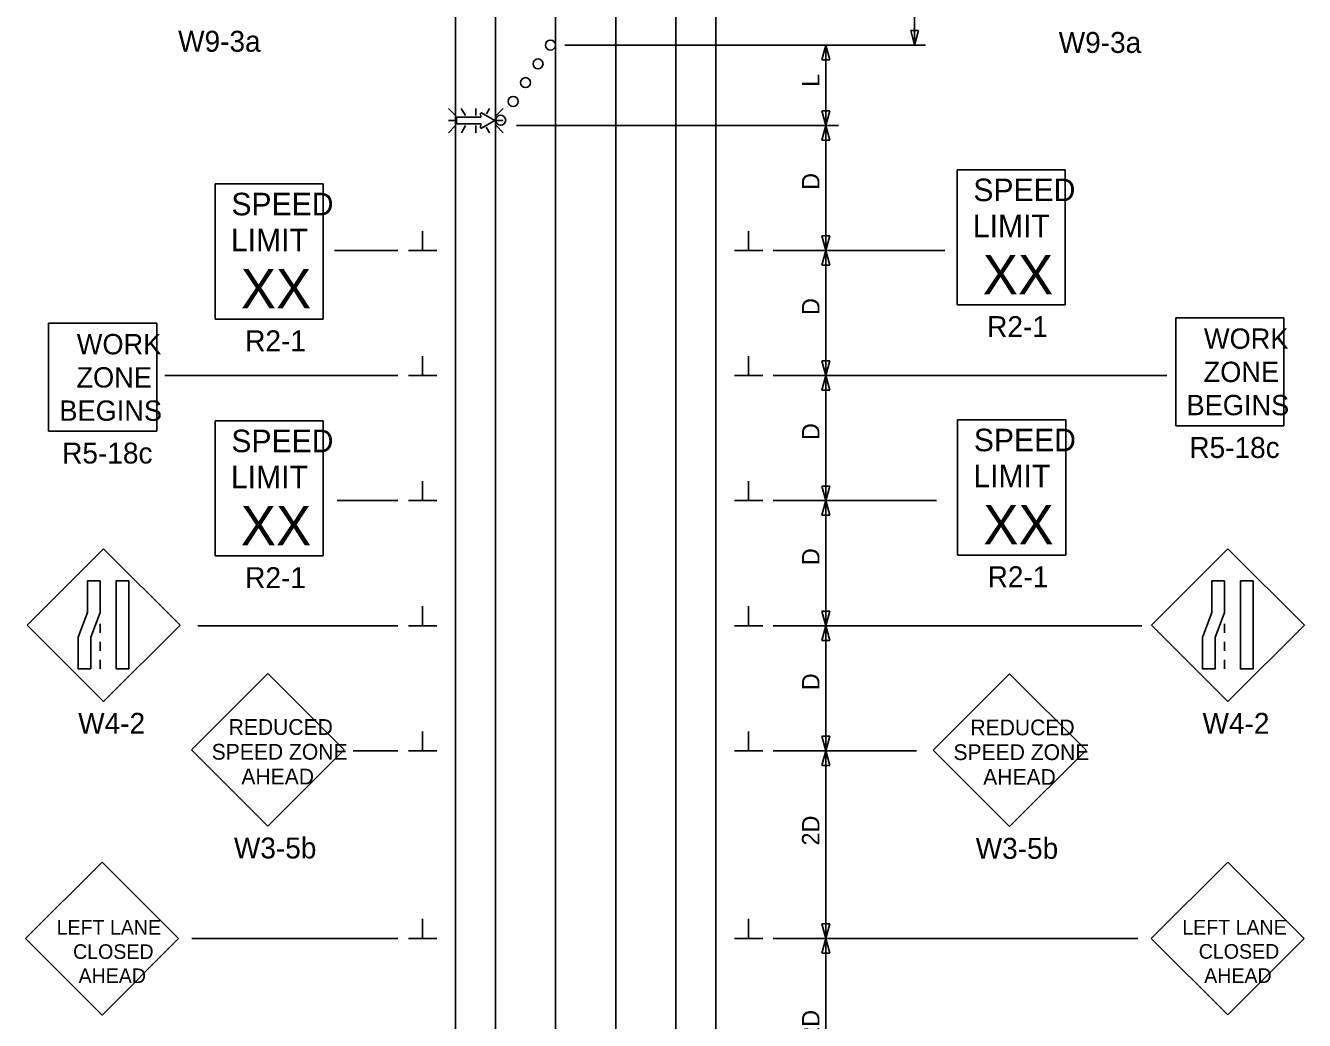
# Model space of a CAD drawing. Extents: x 16726 to 18482, y 5650 to 7013.
# Drawn here: x 16732 to 17243, y 6168 to 6566 of the extents above; entities that cross this region are included whole.
import ezdxf

# ---------------------------------------------------------------- set-up
doc = ezdxf.new("R2010")
doc.units = 0
for name, color, linetype in [('ALI_LEGAL_EX', 7, 'Continuous'), ('Level 6', 7, 'Continuous'), ('PAVT_EDGE_EX', 7, 'Continuous'), ('TRAFFIC_SIGNS_PR', 7, 'Continuous'), ('TYPICAL_TEXT_DIMEN_PR', 7, 'Continuous')]:
    doc.layers.add(name, color=color, linetype=linetype)

msp = doc.modelspace()

# ---------------------------------------------------------------- linework, layer by layer
at = {"layer": 'ALI_LEGAL_EX'}
for p, q in [((16943.36, 7013.47), (16943.36, 6195.33)), ((16967.36, 7013.47), (16967.36, 6195.33)), ((16943.36, 6961.56), (16943.36, 6097.65)), ((16967.36, 6961.56), (16967.36, 6097.65))]:
    msp.add_line(p, q, dxfattribs=at)
for points in [[(16943.36, 6524.34), (16943.36, 6499.34)], [(16943.36, 6524.34), (16943.36, 6499.34)], [(16943.36, 6524.34), (16943.36, 6499.34)], [(16943.36, 6524.34), (16943.36, 6499.34)], [(16943.36, 6524.34), (16943.36, 6499.34)], [(16967.36, 6524.34), (16967.36, 6499.34)], [(16967.36, 6524.34), (16967.36, 6499.34)], [(16967.36, 6524.34), (16967.36, 6499.34)], [(16967.36, 6524.34), (16967.36, 6499.34)], [(16967.36, 6524.34), (16967.36, 6499.34)], [(16943.36, 6424.34), (16943.36, 6399.34)], [(16943.36, 6424.34), (16943.36, 6399.34)], [(16943.36, 6424.34), (16943.36, 6399.34)], [(16943.36, 6424.34), (16943.36, 6399.34)], [(16943.36, 6424.34), (16943.36, 6399.34)], [(16967.36, 6424.34), (16967.36, 6399.34)], [(16967.36, 6424.34), (16967.36, 6399.34)], [(16967.36, 6424.34), (16967.36, 6399.34)], [(16967.36, 6424.34), (16967.36, 6399.34)], [(16967.36, 6424.34), (16967.36, 6399.34)], [(16943.36, 6324.34), (16943.36, 6299.34)], [(16943.36, 6324.34), (16943.36, 6299.34)], [(16943.36, 6324.34), (16943.36, 6299.34)], [(16943.36, 6324.34), (16943.36, 6299.34)], [(16943.36, 6324.34), (16943.36, 6299.34)], [(16967.36, 6324.34), (16967.36, 6299.34)], [(16967.36, 6324.34), (16967.36, 6299.34)], [(16967.36, 6324.34), (16967.36, 6299.34)], [(16967.36, 6324.34), (16967.36, 6299.34)], [(16967.36, 6324.34), (16967.36, 6299.34)], [(16943.36, 6224.34), (16943.36, 6199.34)], [(16943.36, 6224.34), (16943.36, 6199.34)], [(16943.36, 6224.34), (16943.36, 6199.34)], [(16943.36, 6224.34), (16943.36, 6199.34)], [(16967.36, 6224.34), (16967.36, 6199.34)], [(16967.36, 6224.34), (16967.36, 6199.34)], [(16967.36, 6224.34), (16967.36, 6199.34)], [(16967.36, 6224.34), (16967.36, 6199.34)], [(16967.36, 6224.34), (16967.36, 6199.34)]]:
    msp.add_lwpolyline(points, dxfattribs=at)
at = {"layer": 'Level 6'}
for p, q in [((16828.35, 6307.2), (16797.81, 6276.66)), ((16858.9, 6276.66), (16828.35, 6307.2)), ((16797.81, 6276.66), (16828.35, 6246.11)), ((16828.35, 6246.11), (16858.9, 6276.66))]:
    msp.add_line(p, q, dxfattribs=at)
at = {"layer": 'PAVT_EDGE_EX'}
for p, q in [((16903.36, 6926.44), (16903.36, 6057.56)), ((16919.36, 6926.44), (16919.36, 6057.56)), ((16991.36, 6926.44), (16991.36, 6057.56)), ((17007.36, 6926.44), (17007.36, 6057.56))]:
    msp.add_line(p, q, dxfattribs=at)
at = {"layer": 'TRAFFIC_SIGNS_PR'}
for p, q in [((16903.38, 6530.22), (16900.56, 6533.04)), ((16905.67, 6533.04), (16907.3, 6530.22)), ((16911.46, 6530.22), (16911.46, 6533.04)), ((16916.93, 6533.04), (16915.72, 6530.95)), ((16922.37, 6533.04), (16919.55, 6530.22)), ((16903.38, 6528.19), (16900.56, 6528.19)), ((16903.38, 6526.16), (16900.56, 6523.34)), ((16907.33, 6526.16), (16905.7, 6523.34)), ((16911.46, 6526.16), (16911.46, 6523.34)), ((16919.55, 6528.19), (16922.37, 6528.19)), ((16922.37, 6523.34), (16919.55, 6526.16)), ((16915.65, 6525.52), (16916.91, 6523.34)), ((17103.8, 6508.51), (17147, 6508.51)), ((17103.8, 6454.51), (17103.8, 6508.51)), ((17147, 6454.51), (17147, 6508.51)), ((16807.3, 6502.86), (16850.5, 6502.86)), ((16807.3, 6448.86), (16807.3, 6502.86)), ((16850.5, 6448.86), (16850.5, 6502.86)), ((17103.8, 6454.51), (17147, 6454.51)), ((16740.76, 6403.98), (16740.76, 6447.18)), ((16740.76, 6447.18), (16783.96, 6447.18)), ((16783.96, 6403.98), (16783.96, 6447.18)), ((16807.3, 6448.86), (16850.5, 6448.86)), ((17191.21, 6406.19), (17191.21, 6449.39)), ((17191.21, 6449.39), (17234.41, 6449.39)), ((17234.41, 6406.19), (17234.41, 6449.39)), ((16740.76, 6403.98), (16783.96, 6403.98)), ((16807.3, 6408.17), (16850.5, 6408.17)), ((16807.3, 6354.17), (16807.3, 6408.17)), ((16850.5, 6354.17), (16850.5, 6408.17)), ((17103.99, 6408.54), (17147.19, 6408.54)), ((17103.99, 6354.54), (17103.99, 6408.54)), ((17147.19, 6354.54), (17147.19, 6408.54)), ((17191.21, 6406.19), (17234.41, 6406.19)), ((16762.75, 6357.04), (16732.2, 6326.5)), ((16793.29, 6326.5), (16762.75, 6357.04)), ((16807.3, 6354.17), (16850.5, 6354.17)), ((17103.99, 6354.54), (17147.19, 6354.54)), ((17212.05, 6357.02), (17181.5, 6326.47)), ((17242.6, 6326.47), (17212.05, 6357.02)), ((16761.34, 6327.05), (16761.34, 6323.45)), ((17210.65, 6327.03), (17210.65, 6323.43)), ((16732.2, 6326.5), (16762.75, 6295.95)), ((16762.75, 6295.95), (16793.29, 6326.5)), ((17181.5, 6326.47), (17212.05, 6295.93)), ((17212.05, 6295.93), (17242.6, 6326.47)), ((16761.34, 6319.85), (16761.34, 6316.25)), ((17210.65, 6319.83), (17210.65, 6316.23)), ((16761.34, 6312.65), (16761.34, 6309.05)), ((17210.65, 6312.63), (17210.65, 6309.03)), ((17124.79, 6307.05), (17094.25, 6276.5)), ((17155.34, 6276.5), (17124.79, 6307.05)), ((17094.25, 6276.5), (17124.79, 6245.96)), ((17124.79, 6245.96), (17155.34, 6276.5)), ((16762.09, 6231.73), (16731.55, 6201.19)), ((16792.64, 6201.19), (16762.09, 6231.73)), ((17211.93, 6231.82), (17181.38, 6201.27)), ((17242.47, 6201.27), (17211.93, 6231.82)), ((16731.55, 6201.19), (16762.09, 6170.64)), ((16762.09, 6170.64), (16792.64, 6201.19)), ((17181.38, 6201.27), (17211.93, 6170.72)), ((17211.93, 6170.72), (17242.47, 6201.27))]:
    msp.add_line(p, q, dxfattribs=at)
for points in [[(16913.29, 6530.87), (16913.52, 6529.58), (16903.8, 6529.58), (16903.8, 6526.83), (16913.52, 6526.83), (16913.29, 6525.53)], [(16913.79, 6525.18), (16919.1, 6528.19), (16913.79, 6531.23)]]:
    msp.add_lwpolyline(points, dxfattribs=at)
for points in [[(16761.34, 6344.2), (16761.34, 6331.62), (16757.58, 6321.63), (16757.58, 6309.05), (16752.53, 6309.05), (16752.53, 6321.63), (16756.29, 6331.62), (16756.29, 6344.2)], [(16772.75, 6344.2), (16772.75, 6309.05), (16767.69, 6309.05), (16767.69, 6344.2)], [(17210.65, 6344.18), (17210.65, 6331.6), (17206.89, 6321.6), (17206.89, 6309.03), (17201.83, 6309.03), (17201.83, 6321.6), (17205.59, 6331.6), (17205.59, 6344.18)], [(17222.05, 6344.18), (17222.05, 6309.03), (17217, 6309.03), (17217, 6344.18)]]:
    msp.add_lwpolyline(points, close=True, dxfattribs=at)
for centre in [(16941.29, 6558.37), (16936.33, 6550.85), (16931.36, 6543.35), (16926.39, 6535.85), (16921.42, 6528.34)]:
    msp.add_circle(centre, 2, dxfattribs=at)
for centre, start, end in [((16913.62, 6530.93), 61.4833, 189.9593), ((16913.62, 6525.47), 170.7308, 298.8916)]:
    msp.add_arc(centre, 0.341, start, end, dxfattribs=at)
at = {"layer": 'TYPICAL_TEXT_DIMEN_PR'}
for p, q in [((17086.84, 6676.24), (17086.84, 6558.37)), ((17086.84, 6558.37), (17085.27, 6564.23)), ((17085.27, 6564.23), (17086.84, 6564.23)), ((17086.84, 6564.23), (17088.41, 6564.23)), ((17088.41, 6564.23), (17086.84, 6558.37)), ((16947.11, 6558.37), (17091.17, 6558.37)), ((17049.79, 6552.51), (17051.36, 6558.37)), ((17051.36, 6558.37), (17051.36, 6526.26)), ((17051.36, 6558.37), (17052.93, 6552.51)), ((17051.36, 6552.51), (17049.79, 6552.51)), ((17052.93, 6552.51), (17051.36, 6552.51)), ((17051.36, 6526.26), (17049.79, 6532.12)), ((17049.79, 6532.12), (17051.36, 6532.12)), ((17051.36, 6532.12), (17052.93, 6532.12)), ((17052.93, 6532.12), (17051.36, 6526.26)), ((16927.76, 6526.26), (17056.36, 6526.26)), ((17049.79, 6520.4), (17051.36, 6526.26)), ((17051.36, 6526.26), (17051.36, 6476.26)), ((17051.36, 6526.26), (17052.93, 6520.4)), ((17051.36, 6520.4), (17049.79, 6520.4)), ((17052.93, 6520.4), (17051.36, 6520.4)), ((16890.23, 6476.26), (16890.23, 6484.05)), ((17020.48, 6476.26), (17020.48, 6484.05)), ((17051.36, 6476.26), (17049.79, 6482.12)), ((17049.79, 6482.12), (17051.36, 6482.12)), ((17051.36, 6482.12), (17052.93, 6482.12)), ((17052.93, 6482.12), (17051.36, 6476.26)), ((16855.01, 6476.26), (16880.36, 6476.26)), ((16884.61, 6476.26), (16895.86, 6476.26)), ((17026.11, 6476.26), (17014.86, 6476.26)), ((17030.36, 6476.26), (17098.92, 6476.26)), ((17049.79, 6470.4), (17051.36, 6476.26)), ((17051.36, 6476.26), (17051.36, 6426.26)), ((17051.36, 6476.26), (17052.93, 6470.4)), ((17051.36, 6470.4), (17049.79, 6470.4)), ((17052.93, 6470.4), (17051.36, 6470.4)), ((16890.23, 6426.26), (16890.23, 6434.05)), ((17020.48, 6426.26), (17020.48, 6434.05)), ((17051.36, 6426.26), (17049.79, 6432.12)), ((17049.79, 6432.12), (17051.36, 6432.12)), ((17051.36, 6432.12), (17052.93, 6432.12)), ((17052.93, 6432.12), (17051.36, 6426.26)), ((16880.36, 6426.26), (16787.26, 6426.26)), ((16884.61, 6426.26), (16895.86, 6426.26)), ((17026.11, 6426.26), (17014.86, 6426.26)), ((17030.36, 6426.26), (17187.63, 6426.26)), ((17030.36, 6426.26), (17095.61, 6426.26)), ((17049.79, 6420.4), (17051.36, 6426.26)), ((17051.36, 6426.26), (17052.93, 6420.4)), ((17051.36, 6426.26), (17051.36, 6376.26)), ((17051.36, 6420.4), (17049.79, 6420.4)), ((17052.93, 6420.4), (17051.36, 6420.4)), ((16890.23, 6376.26), (16890.23, 6384.05)), ((17020.48, 6376.26), (17020.48, 6384.05)), ((17051.36, 6376.26), (17049.79, 6382.12)), ((17049.79, 6382.12), (17051.36, 6382.12)), ((17051.36, 6382.12), (17052.93, 6382.12)), ((17052.93, 6382.12), (17051.36, 6376.26)), ((16880.36, 6376.26), (16856.12, 6376.26)), ((16884.61, 6376.26), (16895.86, 6376.26)), ((17026.11, 6376.26), (17014.86, 6376.26)), ((17030.36, 6376.26), (17095.61, 6376.26)), ((17049.79, 6370.4), (17051.36, 6376.26)), ((17051.36, 6376.26), (17051.36, 6326.26)), ((17051.36, 6376.26), (17052.93, 6370.4)), ((17051.36, 6370.4), (17049.79, 6370.4)), ((17052.93, 6370.4), (17051.36, 6370.4)), ((16890.23, 6326.26), (16890.23, 6334.05)), ((17020.48, 6326.26), (17020.48, 6334.05)), ((17051.36, 6326.26), (17049.79, 6332.12)), ((17049.79, 6332.12), (17051.36, 6332.12)), ((17051.36, 6332.12), (17052.93, 6332.12)), ((17052.93, 6332.12), (17051.36, 6326.26)), ((16800.38, 6326.26), (16880.36, 6326.26)), ((16884.61, 6326.26), (16895.86, 6326.26)), ((17026.11, 6326.26), (17014.86, 6326.26)), ((17030.36, 6326.26), (17177.56, 6326.26)), ((17049.79, 6320.4), (17051.36, 6326.26)), ((17051.36, 6326.26), (17051.36, 6276.26)), ((17051.36, 6326.26), (17052.93, 6320.4)), ((17051.36, 6320.4), (17049.79, 6320.4)), ((17052.93, 6320.4), (17051.36, 6320.4)), ((16890.23, 6276.26), (16890.23, 6284.05)), ((17020.48, 6276.26), (17020.48, 6284.05)), ((17051.36, 6276.26), (17049.79, 6282.12)), ((17049.79, 6282.12), (17051.36, 6282.12)), ((17051.36, 6282.12), (17052.93, 6282.12)), ((17052.93, 6282.12), (17051.36, 6276.26)), ((16862.47, 6276.26), (16880.36, 6276.26)), ((16884.61, 6276.26), (16895.86, 6276.26)), ((17026.11, 6276.26), (17014.86, 6276.26)), ((17030.36, 6276.26), (17087.57, 6276.26)), ((17049.79, 6270.4), (17051.36, 6276.26)), ((17051.36, 6276.26), (17051.36, 6201.26)), ((17051.36, 6276.26), (17052.93, 6270.4)), ((17051.36, 6270.4), (17049.79, 6270.4)), ((17052.93, 6270.4), (17051.36, 6270.4)), ((16890.23, 6201.26), (16890.23, 6209.05)), ((17020.48, 6201.26), (17020.48, 6209.05)), ((17051.36, 6201.26), (17049.79, 6207.12)), ((17049.79, 6207.12), (17051.36, 6207.12)), ((17051.36, 6207.12), (17052.93, 6207.12)), ((17052.93, 6207.12), (17051.36, 6201.26)), ((16798, 6201.26), (16880.36, 6201.26)), ((16884.61, 6201.26), (16895.86, 6201.26)), ((17026.11, 6201.26), (17014.86, 6201.26)), ((17030.36, 6201.26), (17175.99, 6201.26)), ((17049.79, 6195.4), (17051.36, 6201.26)), ((17051.36, 6201.26), (17051.36, 6126.26)), ((17051.36, 6201.26), (17052.93, 6195.4)), ((17051.36, 6195.4), (17049.79, 6195.4)), ((17052.93, 6195.4), (17051.36, 6195.4))]:
    msp.add_line(p, q, dxfattribs=at)

# ---------------------------------------------------------------- texts
at = {"layer": 'Level 6'}
for s, height, p in [('REDUCED', 6.3, (16812.67, 6282.63)), ('SPEED ZONE', 6.3, (16805.91, 6272.73)), ('AHEAD', 6.3, (16817.79, 6262.83)), ('W3-5b', 8.37, (16814.8, 6233.24))]:
    msp.add_text(s, height=height, dxfattribs=at).set_placement(p)
at = {"layer": 'TRAFFIC_SIGNS_PR'}
for s, height, p in [('W9-3a', 8.37, (16792.51, 6555.71)), ('W9-3a', 8.37, (17144.41, 6555.24)), ('SPEED', 9, (17110.29, 6495.98)), ('SPEED', 9, (16813.79, 6490.33)), ('LIMIT', 9, (17110.1, 6481.58)), ('LIMIT', 9, (16813.61, 6475.93)), ('XX', 15.785, (17114.05, 6458.74)), ('XX', 15.785, (16817.55, 6453.09)), ('R2-1', 8.37, (17115.81, 6441.64)), ('R2-1', 8.37, (16819.31, 6435.99)), ('WORK', 8.119, (17202.45, 6436.98)), ('WORK', 8.119, (16752.01, 6434.77)), ('ZONE', 8.119, (16751.88, 6421.48)), ('ZONE', 8.119, (17202.32, 6423.69)), ('BEGINS', 8.119, (16745.05, 6408.19)), ('BEGINS', 8.119, (17195.49, 6410.41)), ('SPEED', 9, (16813.79, 6395.64)), ('SPEED', 9, (17110.48, 6396.01)), ('R5-18c', 8.37, (16746.18, 6391.11)), ('R5-18c', 8.37, (17196.62, 6393.32)), ('LIMIT', 9, (16813.61, 6381.24)), ('LIMIT', 9, (17110.3, 6381.61)), ('XX', 15.785, (16817.55, 6358.4)), ('XX', 15.785, (17114.25, 6358.77)), ('R2-1', 8.37, (16819.31, 6341.3)), ('R2-1', 8.37, (17116, 6341.67)), ('W4-2', 8.37, (16752.57, 6283.08)), ('W4-2', 8.37, (17201.88, 6283.06)), ('REDUCED', 6.3, (17109.11, 6282.47)), ('SPEED ZONE', 6.3, (17102.35, 6272.57)), ('AHEAD', 6.3, (17114.23, 6262.67)), ('W3-5b', 8.37, (17111.24, 6233.09)), ('LEFT LANE', 5.85, (16743.96, 6202.76)), ('LEFT LANE', 5.85, (17193.8, 6202.84)), ('CLOSED', 5.85, (17200.36, 6193.17)), ('CLOSED', 5.85, (16750.52, 6193.08)), ('AHEAD', 5.85, (16752.71, 6183.41)), ('AHEAD', 5.85, (17202.55, 6183.49))]:
    msp.add_text(s, height=height, dxfattribs=at).set_placement(p)
at = {"layer": 'TYPICAL_TEXT_DIMEN_PR'}
for s, p in [('L', (17048.8, 6541.67)), ('D', (17048.8, 6500.48)), ('D', (17048.8, 6450.48)), ('D', (17048.8, 6400.48)), ('D', (17048.8, 6350.48)), ('D', (17048.8, 6300.48)), ('2D', (17048.8, 6238.42)), ('2D', (17048.8, 6160.73))]:
    msp.add_text(s, height=7, rotation=90, dxfattribs=at).set_placement(p)

doc.saveas('drawing.dxf')
